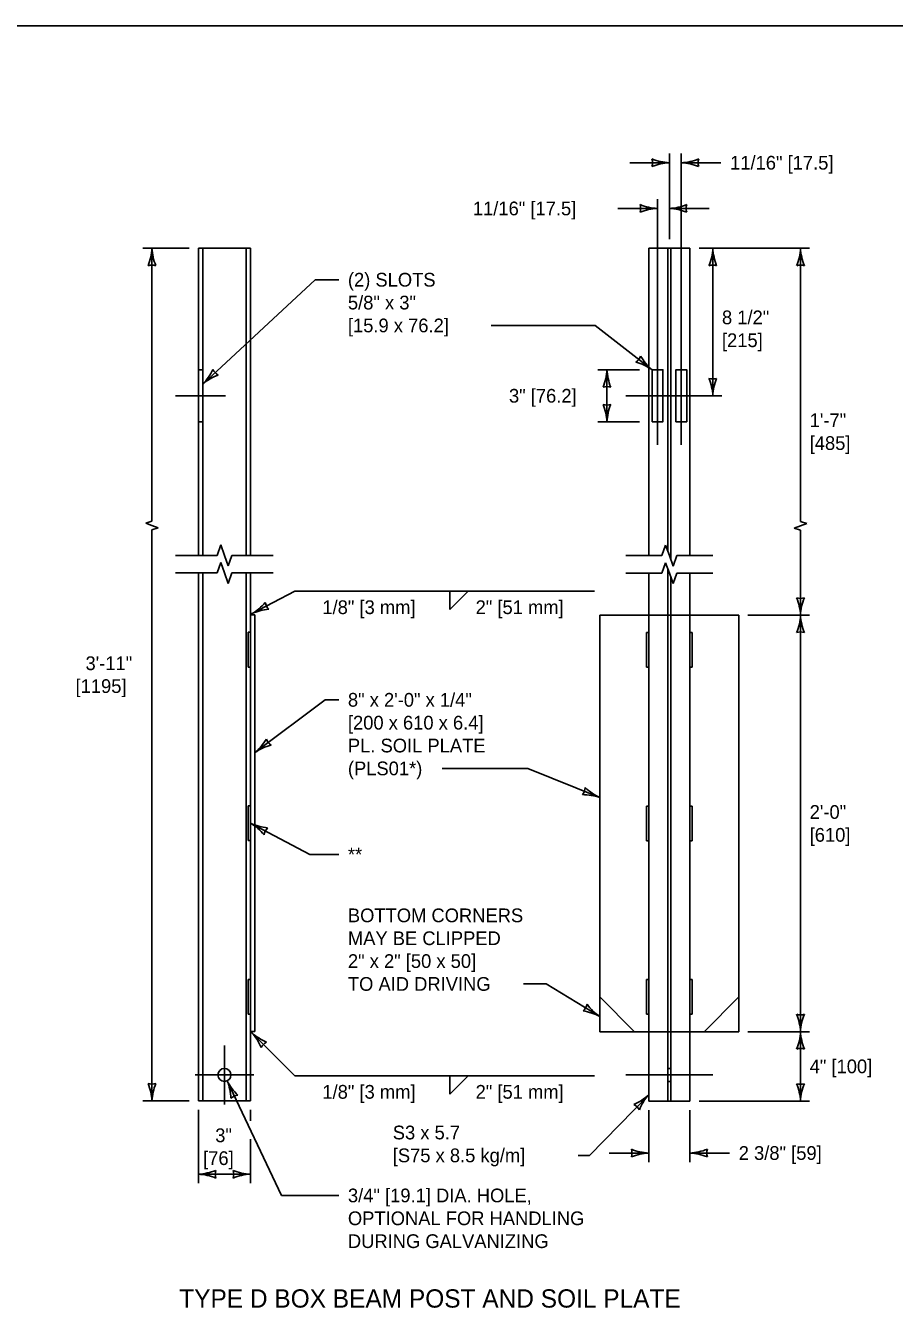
# Model space of a CAD drawing. Extents: x 49991.4 to 50021, y 49987.6 to 50011.4.
# Drawn here: x 50008.26 to 50012.05, y 49993.37 to 49999 of the extents above; entities that cross this region are included whole.
import ezdxf

# ---------------------------------------------------------------- set-up
doc = ezdxf.new("R2010")
doc.units = 0
for name, color, linetype in [('Level 1', 7, 'Continuous'), ('Level 2', 7, 'Continuous'), ('Level 3', 7, 'Continuous'), ('Level 4', 7, 'Continuous'), ('Level 5', 7, 'Continuous'), ('Level 6', 7, 'Continuous')]:
    doc.layers.add(name, color=color, linetype=linetype)

msp = doc.modelspace()

# ---------------------------------------------------------------- linework, layer by layer
at = {"layer": 'Level 1'}
for p, q in [((50009.0104, 49996.6829), (50009.0104, 49998.0259)), ((50009.0104, 49998.0259), (50009.2379, 49998.0259)), ((50009.0294, 49996.6829), (50009.0294, 49998.0259)), ((50009.219, 49996.6829), (50009.219, 49998.0259)), ((50009.2379, 49996.6829), (50009.2379, 49998.0259)), ((50010.9804, 49998.0259), (50011.1607, 49998.0259)), ((50010.9804, 49998.0259), (50010.9804, 49996.6819)), ((50011.1607, 49998.0259), (50011.1607, 49996.6819)), ((50009.0104, 49994.297), (50009.0104, 49996.6061)), ((50009.0294, 49994.297), (50009.0294, 49996.6061)), ((50009.2192, 49994.297), (50009.2192, 49996.6061)), ((50009.2381, 49994.297), (50009.2381, 49996.6061)), ((50010.9804, 49996.6051), (50010.9804, 49994.296)), ((50011.1607, 49996.6051), (50011.1607, 49994.296)), ((50009.2571, 49996.4222), (50009.2381, 49996.4222)), ((50009.2571, 49994.6006), (50009.2571, 49996.4222)), ((50010.7669, 49994.5996), (50010.7669, 49996.4212)), ((50010.7669, 49996.4212), (50010.9804, 49996.4212)), ((50011.1607, 49996.4212), (50011.3742, 49996.4212)), ((50011.3742, 49994.5996), (50011.3742, 49996.4212)), ((50009.2381, 49996.3463), (50009.2284, 49996.3463)), ((50009.2284, 49996.3463), (50009.2284, 49996.1945)), ((50009.2381, 49996.1945), (50009.2381, 49996.3463)), ((50010.9804, 49996.3453), (50010.9707, 49996.3453)), ((50010.9707, 49996.3453), (50010.9707, 49996.1935)), ((50010.9804, 49996.1935), (50010.9804, 49996.3453)), ((50011.1704, 49996.3453), (50011.1607, 49996.3453)), ((50011.1607, 49996.3453), (50011.1607, 49996.1935)), ((50011.1704, 49996.1935), (50011.1704, 49996.3453)), ((50009.2284, 49996.1945), (50009.2381, 49996.1945)), ((50010.9707, 49996.1935), (50010.9804, 49996.1935)), ((50011.1607, 49996.1935), (50011.1704, 49996.1935)), ((50009.2381, 49995.5873), (50009.2284, 49995.5873)), ((50009.2284, 49995.5873), (50009.2284, 49995.4355)), ((50009.2381, 49995.4355), (50009.2381, 49995.5873)), ((50010.9804, 49995.5863), (50010.9707, 49995.5863)), ((50010.9707, 49995.5863), (50010.9707, 49995.4345)), ((50010.9804, 49995.4345), (50010.9804, 49995.5863)), ((50011.1704, 49995.5863), (50011.1607, 49995.5863)), ((50011.1607, 49995.5863), (50011.1607, 49995.4345)), ((50011.1704, 49995.4345), (50011.1704, 49995.5863)), ((50009.2284, 49995.4355), (50009.2381, 49995.4355)), ((50010.9707, 49995.4345), (50010.9804, 49995.4345)), ((50011.1607, 49995.4345), (50011.1704, 49995.4345)), ((50009.2381, 49994.8283), (50009.2284, 49994.8283)), ((50009.2284, 49994.8283), (50009.2284, 49994.6765)), ((50009.2381, 49994.6765), (50009.2381, 49994.8283)), ((50010.9804, 49994.8273), (50010.9707, 49994.8273)), ((50010.9707, 49994.8273), (50010.9707, 49994.6755)), ((50010.9804, 49994.6755), (50010.9804, 49994.8273)), ((50011.1704, 49994.8273), (50011.1607, 49994.8273)), ((50011.1607, 49994.8273), (50011.1607, 49994.6755)), ((50011.1704, 49994.6755), (50011.1704, 49994.8273)), ((50009.2284, 49994.6765), (50009.2381, 49994.6765)), ((50010.9707, 49994.6755), (50010.9804, 49994.6755)), ((50011.1607, 49994.6755), (50011.1704, 49994.6755)), ((50009.2571, 49994.6006), (50009.2381, 49994.6006)), ((50010.7669, 49994.5996), (50010.9804, 49994.5996)), ((50011.1607, 49994.5996), (50011.3742, 49994.5996)), ((50009.2381, 49994.297), (50009.0104, 49994.297)), ((50010.9804, 49994.296), (50011.1607, 49994.296))]:
    msp.add_line(p, q, dxfattribs=at)
for points in [[(49999.3835, 49998.9992), (50016.7501, 49998.9992), (50016.7501, 49987.7988), (49999.3835, 49987.7988)], [(50010.9947, 49997.2669), (50010.9947, 49997.4946), (50011.0421, 49997.4946), (50011.0421, 49997.2669)], [(50011.1465, 49997.2669), (50011.1465, 49997.4946), (50011.099, 49997.4946), (50011.099, 49997.2669)]]:
    msp.add_lwpolyline(points, close=True, dxfattribs=at)
for points in [[(50009.2381, 49996.4319), (50009.2381, 49996.4222), (50009.2478, 49996.4222), (50009.2381, 49996.4319)], [(50009.2381, 49994.5909), (50009.2381, 49994.6006), (50009.2478, 49994.6006), (50009.2381, 49994.5909)]]:
    msp.add_lwpolyline(points, dxfattribs=at)
msp.add_circle((50009.1243, 49994.4101), 0.0285, dxfattribs=at)
at = {"layer": 'Level 3'}
for p, q in [((50011.0706, 49998.4001), (50010.8971, 49998.4001)), ((50011.0706, 49998.0659), (50011.0706, 49998.4401)), ((50011.1227, 49998.4001), (50011.2962, 49998.4001)), ((50011.0184, 49998.2001), (50010.8449, 49998.2001)), ((50011.0706, 49998.2001), (50011.244, 49998.2001)), ((50008.9704, 49998.0259), (50008.7673, 49998.0259)), ((50008.8073, 49998.0259), (50008.8073, 49996.833)), ((50011.2007, 49998.0259), (50011.6843, 49998.0259)), ((50011.2607, 49997.3808), (50011.2607, 49998.0259)), ((50011.6443, 49996.8315), (50011.6443, 49998.0259)), ((50009.0294, 49997.432), (50009.5205, 49997.8884)), ((50009.5205, 49997.8884), (50009.6244, 49997.8884)), ((50010.2906, 49997.6884), (50010.7461, 49997.6884)), ((50010.7461, 49997.6884), (50010.9947, 49997.4946)), ((50010.9404, 49997.4946), (50010.7576, 49997.4946)), ((50010.7976, 49997.4946), (50010.7976, 49997.2669)), ((50010.9404, 49997.2669), (50010.7576, 49997.2669)), ((50008.7799, 49996.8233), (50008.8073, 49996.833)), ((50008.7799, 49996.8233), (50008.8073, 49996.8136)), ((50011.6717, 49996.8218), (50011.6443, 49996.8315)), ((50011.6717, 49996.8218), (50011.6443, 49996.8121)), ((50008.8073, 49996.8136), (50008.8347, 49996.8039)), ((50008.8073, 49996.7942), (50008.8347, 49996.8039)), ((50008.8073, 49996.7942), (50008.8073, 49994.297)), ((50011.6443, 49996.8121), (50011.6169, 49996.8024)), ((50011.6443, 49996.7927), (50011.6169, 49996.8024)), ((50011.6443, 49996.4212), (50011.6443, 49996.7927)), ((50009.243, 49996.427), (50009.4323, 49996.526)), ((50009.4323, 49996.526), (50010.7432, 49996.526)), ((50010.1099, 49996.446), (50010.1899, 49996.526)), ((50010.1099, 49996.526), (50010.1099, 49996.446)), ((50011.4142, 49996.4212), (50011.6843, 49996.4212)), ((50011.6443, 49994.5996), (50011.6443, 49996.4212)), ((50009.5645, 49996.051), (50009.2571, 49995.8201)), ((50009.5645, 49996.051), (50009.6244, 49996.051)), ((50010.0766, 49995.751), (50010.4513, 49995.751)), ((50010.4513, 49995.751), (50010.7669, 49995.6233)), ((50009.2381, 49995.5114), (50009.4976, 49995.3745)), ((50009.6244, 49995.3745), (50009.4976, 49995.3745)), ((50010.4318, 49994.8083), (50010.5316, 49994.8083)), ((50010.5316, 49994.8083), (50010.7669, 49994.6655)), ((50009.243, 49994.5957), (50009.4323, 49994.4064)), ((50011.4141, 49994.5996), (50011.6842, 49994.5996)), ((50011.6443, 49994.296), (50011.6443, 49994.5996)), ((50009.4323, 49994.4064), (50010.7432, 49994.4064)), ((50010.1099, 49994.3264), (50010.1899, 49994.4064)), ((50010.1099, 49994.4064), (50010.1099, 49994.3264)), ((50009.374, 49993.8833), (50009.1365, 49994.3844)), ((50008.9704, 49994.297), (50008.7673, 49994.297)), ((50010.7212, 49994.0585), (50010.9804, 49994.324)), ((50011.2007, 49994.296), (50011.6842, 49994.296)), ((50009.0104, 49994.257), (50009.0104, 49993.9363)), ((50009.2381, 49994.257), (50009.2381, 49994.2099)), ((50010.9804, 49994.256), (50010.9804, 49994.0288)), ((50011.1607, 49994.256), (50011.1607, 49994.0288)), ((50009.2381, 49994.1299), (50009.2381, 49993.9363)), ((50010.807, 49994.0688), (50010.9804, 49994.0688)), ((50011.1607, 49994.0688), (50011.3341, 49994.0688)), ((50010.6719, 49994.0585), (50010.7212, 49994.0585)), ((50009.0104, 49993.9763), (50009.2381, 49993.9763)), ((50009.374, 49993.8833), (50009.6244, 49993.8833))]:
    msp.add_line(p, q, dxfattribs=at)
for centre, radius, start, end in [((50010.9423, 49998.4001), 0.0548, 342.1388, 17.8612), ((50011.0821, 49998.6328), 0.233, 247.9228, 267.1727), ((50011.0797, 49998.1779), 0.2223, 92.3605, 112.544), ((50011.1136, 49998.6222), 0.2223, 272.3605, 292.544), ((50011.1112, 49998.1674), 0.233, 67.9228, 87.1727), ((50011.251, 49998.4001), 0.0548, 162.1388, 197.8612), ((50011.0275, 49998.4222), 0.2223, 247.456, 267.6395), ((50010.8902, 49998.2001), 0.0548, 342.1388, 17.8612), ((50011.0299, 49997.9674), 0.233, 92.8273, 112.0772), ((50011.0591, 49998.4328), 0.233, 272.8273, 292.0772), ((50011.0614, 49997.9779), 0.2223, 67.456, 87.6395), ((50011.1988, 49998.2001), 0.0548, 162.1388, 197.8612), ((50008.5745, 49998.0374), 0.233, 337.9228, 357.1727), ((50009.0294, 49998.0351), 0.2223, 182.3605, 202.544), ((50011.0386, 49998.0351), 0.2223, 337.456, 357.6395), ((50011.4934, 49998.0374), 0.233, 182.8273, 202.0772), ((50011.4221, 49998.0351), 0.2223, 337.456, 357.6395), ((50011.877, 49998.0374), 0.233, 182.8273, 202.0772), ((50008.8073, 49997.8977), 0.0548, 72.1388, 107.8612), ((50011.2607, 49997.8977), 0.0548, 72.1388, 107.8612), ((50011.6443, 49997.8977), 0.0548, 72.1388, 107.8612), ((50010.8935, 49997.5735), 0.0548, 304.2034, 339.9258), ((50011.1384, 49997.6642), 0.2223, 209.5206, 229.7041), ((50008.8626, 49997.5947), 0.233, 315.7269, 334.9767), ((50009.1233, 49997.5193), 0.0548, 205.0384, 240.7608), ((50010.8607, 49997.304), 0.233, 54.8919, 74.1418), ((50009.1739, 49997.263), 0.2223, 110.3556, 130.5391), ((50010.5754, 49997.5038), 0.2223, 337.456, 357.6395), ((50011.0303, 49997.5061), 0.233, 182.8273, 202.0772), ((50011.2607, 49997.509), 0.0548, 252.1388, 287.8612), ((50011.028, 49997.3693), 0.233, 2.8273, 22.0772), ((50011.4828, 49997.3716), 0.2223, 157.456, 177.6395), ((50010.7976, 49997.3664), 0.0548, 72.1388, 107.8612), ((50010.7976, 49997.3952), 0.0548, 252.1388, 287.8612), ((50010.5649, 49997.2555), 0.233, 2.8273, 22.0772), ((50011.0197, 49997.2578), 0.2223, 157.456, 177.6395), ((50011.6443, 49996.5494), 0.0548, 252.1388, 287.8612), ((50011.4115, 49996.4097), 0.233, 2.8273, 22.0772), ((50011.8664, 49996.412), 0.2223, 157.456, 177.6395), ((50009.132, 49996.6197), 0.2223, 299.9519, 320.1354), ((50009.3406, 49996.2155), 0.233, 95.5143, 114.7641), ((50009.3566, 49996.4864), 0.0548, 189.7302, 225.4526), ((50011.4221, 49996.4303), 0.2223, 337.456, 357.6395), ((50011.877, 49996.4327), 0.233, 182.8273, 202.0772), ((50011.6443, 49996.293), 0.0548, 72.1388, 107.8612), ((50009.1082, 49995.9993), 0.233, 309.7351, 328.985), ((50009.3596, 49995.8971), 0.0548, 199.0467, 234.769), ((50009.3832, 49995.637), 0.2223, 104.3638, 124.5474), ((50010.6481, 49995.6713), 0.0548, 320.1085, 355.8309), ((50010.8588, 49995.8257), 0.2223, 225.4257, 245.6092), ((50010.6903, 49995.4032), 0.233, 70.797, 90.0468), ((50009.1264, 49995.3192), 0.2223, 39.6425, 59.826), ((50009.3366, 49995.7226), 0.233, 245.0138, 264.2636), ((50009.3515, 49995.4516), 0.0548, 134.3253, 170.0476), ((50010.6573, 49994.732), 0.0548, 310.8765, 346.5988), ((50010.656, 49994.4606), 0.233, 61.5649, 80.8148), ((50010.89, 49994.8506), 0.2223, 216.1936, 236.3772), ((50011.6443, 49994.7278), 0.0548, 252.1388, 287.8612), ((50011.4115, 49994.5881), 0.233, 2.8273, 22.0772), ((50011.8664, 49994.5904), 0.2223, 157.456, 177.6395), ((50009.0794, 49994.4451), 0.2223, 22.456, 42.6395), ((50009.3994, 49994.7684), 0.233, 227.8273, 247.0772), ((50011.4221, 49994.6087), 0.2223, 337.456, 357.6395), ((50011.877, 49994.6111), 0.233, 182.8273, 202.0772), ((50009.3337, 49994.5051), 0.0548, 117.1388, 152.8612), ((50011.6443, 49994.4714), 0.0548, 72.1388, 107.8612), ((50008.5851, 49994.2878), 0.2223, 2.3605, 22.544), ((50008.8073, 49994.4252), 0.0548, 252.1388, 287.8612), ((50009.04, 49994.2855), 0.233, 157.9228, 177.1727), ((50008.9301, 49994.3018), 0.2223, 1.6303, 21.8138), ((50009.3441, 49994.4902), 0.233, 207.0016, 226.2515), ((50011.6443, 49994.4242), 0.0548, 252.1388, 287.8612), ((50011.4115, 49994.2845), 0.233, 2.8273, 22.0772), ((50011.8664, 49994.2868), 0.2223, 157.456, 177.6395), ((50009.189, 49994.2674), 0.0548, 96.3131, 132.0355), ((50010.8279, 49994.4857), 0.2223, 293.1356, 313.3191), ((50011.1549, 49994.1696), 0.233, 138.5069, 157.7567), ((50010.8908, 49994.2322), 0.0548, 27.8184, 63.5407), ((50010.9896, 49994.2909), 0.2223, 247.456, 267.6395), ((50010.8522, 49994.0688), 0.0548, 342.1388, 17.8612), ((50010.9919, 49993.8361), 0.233, 92.8273, 112.0772), ((50011.1492, 49994.3015), 0.233, 272.8273, 292.0772), ((50011.1515, 49993.8466), 0.2223, 67.456, 87.6395), ((50011.2889, 49994.0688), 0.0548, 162.1388, 197.8612), ((50008.9989, 49994.209), 0.233, 272.8273, 292.0772), ((50009.0013, 49993.7541), 0.2223, 67.456, 87.6395), ((50009.1387, 49993.9763), 0.0548, 162.1388, 197.8612), ((50009.2473, 49994.1984), 0.2223, 247.456, 267.6395), ((50009.1099, 49993.9763), 0.0548, 342.1388, 17.8612), ((50009.2496, 49993.7436), 0.233, 92.8273, 112.0772)]:
    msp.add_arc(centre, radius, start, end, dxfattribs=at)
at = {"layer": 'Level 4'}
for p, q in [((50011.0634, 49996.702), (50011.0634, 49998.0259)), ((50011.0777, 49996.6618), (50011.0777, 49998.0259)), ((50009.0104, 49997.4946), (50009.0294, 49997.4946)), ((50009.0104, 49997.2669), (50009.0294, 49997.2669)), ((50011.0634, 49996.6252), (50011.0634, 49994.296)), ((50011.0777, 49996.585), (50011.0777, 49994.296)), ((50010.9804, 49996.4212), (50011.1607, 49996.4212)), ((50010.7669, 49994.7514), (50010.9187, 49994.5996)), ((50011.2224, 49994.5996), (50011.3742, 49994.7514)), ((50010.9804, 49994.5996), (50011.1607, 49994.5996)), ((50011.0634, 49994.4386), (50011.0777, 49994.4386)), ((50011.0634, 49994.3816), (50011.0777, 49994.3816))]:
    msp.add_line(p, q, dxfattribs=at)
at = {"layer": 'Level 5'}
for p, q in [((50011.1227, 49998.4401), (50011.1227, 49997.1669)), ((50011.0184, 49998.2401), (50011.0184, 49997.1669)), ((50008.9104, 49997.3808), (50009.1294, 49997.3808)), ((50010.8804, 49997.3808), (50011.3007, 49997.3808)), ((50009.1243, 49994.5386), (50009.1243, 49994.2816)), ((50008.9958, 49994.4101), (50009.2528, 49994.4101)), ((50010.8804, 49994.4101), (50011.2607, 49994.4101))]:
    msp.add_line(p, q, dxfattribs=at)
at = {"layer": 'Level 6'}
for p, q in [((50009.108, 49996.7286), (50009.0918, 49996.6829)), ((50009.108, 49996.7286), (50009.1242, 49996.6829)), ((50011.0544, 49996.7276), (50011.0382, 49996.6819)), ((50011.0544, 49996.7276), (50011.0706, 49996.6819)), ((50008.9104, 49996.6829), (50009.0918, 49996.6829)), ((50009.108, 49996.6518), (50009.0918, 49996.6061)), ((50009.108, 49996.6518), (50009.1242, 49996.6061)), ((50009.1242, 49996.6829), (50009.1404, 49996.6372)), ((50009.1566, 49996.6829), (50009.1404, 49996.6372)), ((50009.1566, 49996.6829), (50009.338, 49996.6829)), ((50010.8804, 49996.6819), (50011.0382, 49996.6819)), ((50011.0544, 49996.6508), (50011.0382, 49996.6051)), ((50011.0544, 49996.6508), (50011.0706, 49996.6051)), ((50011.0706, 49996.6819), (50011.0868, 49996.6362)), ((50011.103, 49996.6819), (50011.0868, 49996.6362)), ((50011.103, 49996.6819), (50011.2607, 49996.6819)), ((50008.9104, 49996.6061), (50009.0918, 49996.6061)), ((50009.1242, 49996.6061), (50009.1404, 49996.5604)), ((50009.1566, 49996.6061), (50009.1404, 49996.5604)), ((50009.1566, 49996.6061), (50009.3381, 49996.6061)), ((50010.8804, 49996.6051), (50011.0382, 49996.6051)), ((50011.0706, 49996.6051), (50011.0868, 49996.5594)), ((50011.103, 49996.6051), (50011.0868, 49996.5594)), ((50011.103, 49996.6051), (50011.2607, 49996.6051))]:
    msp.add_line(p, q, dxfattribs=at)

# ---------------------------------------------------------------- texts
at = {"layer": 'Level 2'}
for s, p in [('11/16" [17.5]', (50011.3362, 49998.3701)), ('11/16" [17.5]', (50010.2111, 49998.1701)), ('3\'-11"', (50008.5165, 49996.181)), ('[1195]', (50008.4729, 49996.081))]:
    msp.add_text(s, height=0.06, rotation=360, dxfattribs=at).set_placement(p)
for s, height, p in [('(2) SLOTS', 0.06, (50009.6644, 49997.8584)), ('5/8" x 3"', 0.06, (50009.6644, 49997.7584)), ('[15.9 x 76.2]', 0.06, (50009.6644, 49997.6584)), ('8 1/2"', 0.06, (50011.3007, 49997.6937)), ('[215]', 0.06, (50011.3007, 49997.5937)), ('3" [76.2]', 0.06, (50010.369, 49997.3508)), ('1\'-7"', 0.06, (50011.6843, 49997.2439)), ('[485]', 0.06, (50011.6843, 49997.1439)), ('1/8" [3 mm]', 0.06, (50009.5527, 49996.426)), ('2" [51 mm]', 0.06, (50010.223, 49996.426)), ('8" x 2\'-0" x 1/4"', 0.06, (50009.6644, 49996.021)), ('[200 x 610 x 6.4]', 0.06, (50009.6644, 49995.921)), ('PL. SOIL PLATE', 0.06, (50009.6644, 49995.821)), ('(PLS01*)', 0.06, (50009.6644, 49995.721)), ('2\'-0"', 0.06, (50011.6843, 49995.5304)), ('[610]', 0.06, (50011.6843, 49995.4304)), ('**', 0.06, (50009.6644, 49995.3445)), ('BOTTOM CORNERS', 0.06, (50009.6644, 49995.0783)), ('MAY BE CLIPPED', 0.06, (50009.6644, 49994.9783)), ('2" x 2" [50 x 50]', 0.06, (50009.6644, 49994.8783)), ('TO AID DRIVING', 0.06, (50009.6644, 49994.7783)), ('4" [100]', 0.06, (50011.6843, 49994.4178)), ('1/8" [3 mm]', 0.06, (50009.5527, 49994.3064)), ('2" [51 mm]', 0.06, (50010.223, 49994.3064)), ('3"', 0.06, (50009.0839, 49994.1163)), ('S3 x 5.7', 0.06, (50009.8606, 49994.1285)), ('[76]', 0.06, (50009.031, 49994.0163)), ('[S75 x 8.5 kg/m]', 0.06, (50009.8606, 49994.0285)), ('2 3/8" [59]', 0.06, (50011.3741, 49994.0388)), ('3/4" [19.1] DIA. HOLE,', 0.06, (50009.6644, 49993.8533)), ('OPTIONAL FOR HANDLING', 0.06, (50009.6644, 49993.7533)), ('DURING GALVANIZING', 0.06, (50009.6644, 49993.6533)), ('TYPE D BOX BEAM POST AND SOIL PLATE', 0.08, (50008.9266, 49993.3927))]:
    msp.add_text(s, height=height, dxfattribs=at).set_placement(p)

doc.saveas('drawing.dxf')
